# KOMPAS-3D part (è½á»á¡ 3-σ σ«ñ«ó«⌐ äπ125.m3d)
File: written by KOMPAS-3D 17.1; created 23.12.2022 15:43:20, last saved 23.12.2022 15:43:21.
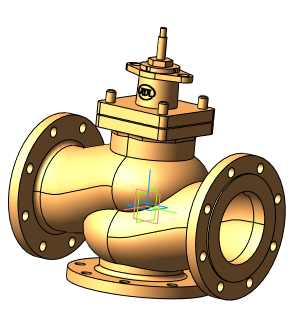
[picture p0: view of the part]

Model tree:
1. Операция без истории:2  (labels: Сталь 20  ГОСТ 1050-2013)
